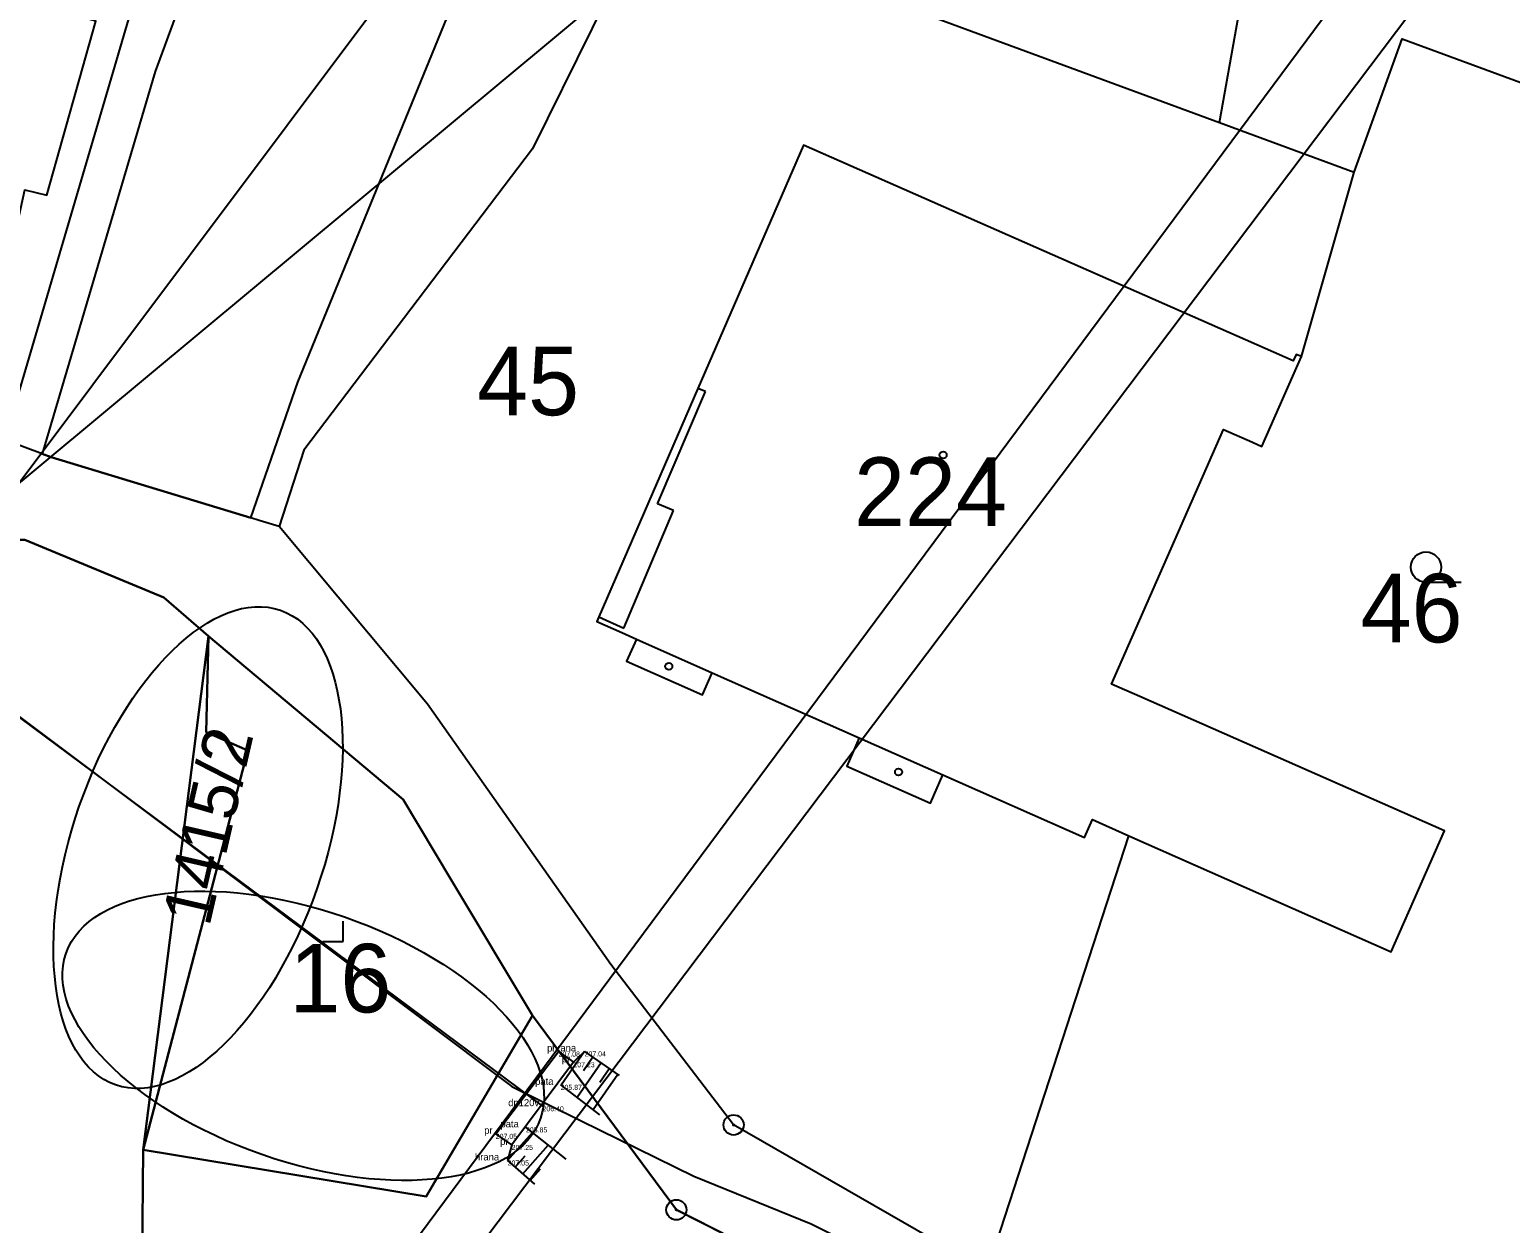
# Model space of a CAD drawing. Extents: x -537341 to -532984, y -1143469 to -1141314.
# Drawn here: x -534057.3 to -533983.8, y -1143098.1 to -1143038.9 of the extents above; entities that cross this region are included whole.
import ezdxf

# ---------------------------------------------------------------- set-up
doc = ezdxf.new("R2010")
doc.units = 0
for name, color, linetype in [('Hranice parcel', 7, 'Continuous'), ('parcelní_č_2000', 7, 'Continuous'), ('u_II_etapa', 7, 'Continuous'), ('u_obec_Horní_Moš', 7, 'Continuous'), ('u_osa_stávající', 7, 'Continuous'), ('u_osa_toku', 7, 'Continuous'), ('u_pricne', 7, 'Continuous'), ('u_ŘSD', 7, 'Continuous'), ('Vnitřní kresba', 7, 'Continuous'), ('Značky bodu BP', 7, 'Continuous'), ('Značky budov', 7, 'Continuous'), ('Značky kultur', 7, 'Continuous'), ('ˇ1', 7, 'Continuous'), ('ˇ12', 7, 'Continuous'), ('ˇ13', 7, 'Continuous'), ('ˇ18', 7, 'Continuous'), ('ˇ3', 7, 'Continuous'), ('ˇ8', 7, 'Continuous'), ('ˇ9', 7, 'Continuous')]:
    doc.layers.add(name, color=color, linetype=linetype)

msp = doc.modelspace()

# ---------------------------------------------------------------- linework, layer by layer
at = {"layer": 'Hranice parcel'}
for p, q in [((-534051.07, -1143040.98), (-534056.69, -1143059.93)), ((-533998.28, -1143043.5), (-533991.6, -1143045.96)), ((-533994.21, -1143055.11), (-533991.6, -1143045.96)), ((-534046.33, -1143063.11), (-534044, -1143056.38)), ((-534056.69, -1143059.93), (-534059.71, -1143058.81)), ((-534051.67, -1143094.44), (-534048.43, -1143068.97)), ((-534009.79, -1143100.45), (-534002.78, -1143078.87)), ((-534051.84, -1143114.55), (-534051.67, -1143094.44))]:
    msp.add_line(p, q, dxfattribs=at)
for points in [[(-534029.93, -1142977.12), (-534030.99, -1142978.87), (-534033.87, -1142990.61), (-534034.9, -1142999.9), (-534043.73, -1143021.03), (-534051.07, -1143040.98)], [(-534044, -1143056.38), (-534033.84, -1143031.57), (-534033.62, -1143024.42), (-534031.82, -1143019.79), (-534025.57, -1143004.98), (-534017.11, -1142985.6), (-534015.33, -1142982.24), (-534014.75, -1142977.48)], [(-534037.83, -1142990.33), (-534051.24, -1143034.42), (-534058.01, -1143057.42), (-534059.71, -1143058.81)], [(-533998.28, -1143043.5), (-533996.76, -1143034.98), (-533991.84, -1143020.44), (-533993.4, -1143019.57)], [(-534023.48, -1143024.37), (-534026.44, -1143032.82), (-534032.36, -1143044.81), (-534043.7, -1143059.75), (-534044.93, -1143063.54)], [(-534023.48, -1143024.37), (-534016.06, -1143027.04), (-534019.25, -1143035.8), (-534011.84, -1143038.52), (-533998.28, -1143043.5)], [(-534061.01, -1143057.76), (-534059.61, -1143051.09), (-534058.54, -1143051.38), (-534057.55, -1143046.84), (-534056.45, -1143047.11), (-534054.02, -1143038.48), (-534068.08, -1143034.65), (-534070.33, -1143043.04), (-534072.14, -1143042.42), (-534074.04, -1143047.26), (-534079.2, -1143053.63)], [(-533991.6, -1143045.96), (-533989.21, -1143039.35), (-533974.11, -1143044.91), (-533978.01, -1143064.66), (-533978.85, -1143064.5), (-533979.24, -1143066.49), (-533976.96, -1143066.84)], [(-533994.21, -1143055.11), (-533994.48, -1143055), (-533994.62, -1143055.32), (-534018.91, -1143044.63), (-534024.15, -1143056.69), (-534029.07, -1143068.02), (-534029.17, -1143068.25), (-534027.93, -1143068.8), (-534027.2, -1143069.12), (-534027.69, -1143070.22), (-534023.93, -1143071.89), (-534023.44, -1143070.79), (-534016.15, -1143074.01), (-534016.77, -1143075.42), (-534012.62, -1143077.25), (-534012, -1143075.85), (-534004.97, -1143078.96), (-534004.57, -1143078.07), (-534002.78, -1143078.87)], [(-534002.78, -1143078.87), (-533989.76, -1143084.63), (-533987.12, -1143078.63), (-534002.23, -1143071.97), (-534003.63, -1143071.35), (-533998.07, -1143058.73), (-533996.64, -1143059.36), (-533996.18, -1143059.57), (-533994.21, -1143055.11)], [(-534056.69, -1143059.93), (-534056.24, -1143060.09), (-534049.16, -1143062.24), (-534046.33, -1143063.11)], [(-534044.93, -1143063.54), (-534045.91, -1143063.24), (-534046.33, -1143063.11)], [(-534009.79, -1143100.45), (-534022.38, -1143093.21), (-534028.47, -1143085.26), (-534037.56, -1143072.35), (-534044.93, -1143063.54)], [(-534048.43, -1143068.97), (-534050.64, -1143067.05), (-534057.55, -1143064.2), (-534057.96, -1143064.19)], [(-534051.67, -1143094.44), (-534046.48, -1143074.64), (-534048.54, -1143073.74), (-534048.43, -1143068.97)], [(-534048.43, -1143068.97), (-534038.78, -1143077.07), (-534036.39, -1143081.05), (-534032.35, -1143087.78)], [(-534032.35, -1143087.78), (-534037.63, -1143096.75), (-534051.67, -1143094.44)], [(-534032.35, -1143087.78), (-534025.22, -1143097.42), (-534003.68, -1143108.33)]]:
    msp.add_lwpolyline(points, dxfattribs=at)
at = {"layer": 'u_II_etapa'}
for centre, major_axis in [((-534048.948, -1143079.456), (-4.091, -11.768)), ((-534048.948, -1143079.456), (-4.091, -11.768)), ((-534043.729, -1143088.789), (-11.768, 4.091)), ((-534043.729, -1143088.789), (-11.768, 4.091))]:
    msp.add_ellipse(centre, major_axis=major_axis, ratio=0.50074, dxfattribs=at)
at = {"layer": 'u_obec_Horní_Moš'}
for p, q in [((-534056.69, -1143059.93), (-534059.71, -1143058.81)), ((-534050.64, -1143067.05), (-534048.43, -1143068.97)), ((-534048.43, -1143068.97), (-534051.67, -1143094.44)), ((-534048.54, -1143073.74), (-534048.43, -1143068.97)), ((-534048.43, -1143068.97), (-534038.78, -1143077.07)), ((-534046.48, -1143074.64), (-534048.54, -1143073.74)), ((-534051.67, -1143094.44), (-534046.48, -1143074.64)), ((-534038.78, -1143077.07), (-534036.39, -1143081.05)), ((-534036.39, -1143081.05), (-534032.35, -1143087.78)), ((-534032.35, -1143087.78), (-534037.63, -1143096.75)), ((-534025.22, -1143097.42), (-534032.35, -1143087.78)), ((-534051.67, -1143094.44), (-534051.84, -1143114.55)), ((-534037.63, -1143096.75), (-534051.67, -1143094.44)), ((-534003.68, -1143108.33), (-534025.22, -1143097.42))]:
    msp.add_line(p, q, dxfattribs=at)
for points in [[(-534046.33, -1143063.11), (-534049.16, -1143062.24), (-534056.24, -1143060.09), (-534056.69, -1143059.93)], [(-534044.93, -1143063.54), (-534045.91, -1143063.24), (-534046.33, -1143063.11)], [(-534009.79, -1143100.45), (-534022.38, -1143093.21), (-534028.47, -1143085.26), (-534037.56, -1143072.35), (-534044.93, -1143063.54)], [(-534057.96, -1143064.19), (-534057.55, -1143064.2), (-534050.64, -1143067.05)], [(-534032.35, -1143087.78), (-534025.22, -1143097.42), (-534003.68, -1143108.33)]]:
    msp.add_lwpolyline(points, dxfattribs=at)
at = {"layer": 'u_osa_stávající'}
msp.add_lwpolyline([(-534029.938, -1143092.998), (-534024.36, -1143095.747), (-534018.539, -1143098.105), (-534002.633, -1143106.063), (-533979.52, -1143113.76), (-533965.652, -1143121.261), (-533942.321, -1143139.25), (-533937.742, -1143147.056), (-533937.262, -1143155.211), (-533938.57, -1143165.939), (-533939.007, -1143180.156), (-533935.954, -1143193.326), (-533920.298, -1143207.368), (-533896.4, -1143226.731), (-533870.016, -1143249.801), (-533856.715, -1143265.326), (-533834.822, -1143282.988), (-533827.265, -1143289.086), (-533803.511, -1143301.304), (-533782.839, -1143320.667), (-533772.417, -1143327.121)], dxfattribs=at)
at = {"layer": 'u_osa_toku'}
msp.add_lwpolyline([(-534255.2, -1143086.242), (-534194.495, -1143118.949), (-534158.208, -1143134.477), (-534141.073, -1143140.275), (-534130.725, -1143142.98), (-534122.661, -1143143.626), (-534114.813, -1143141.462), (-534105.041, -1143135.691), (-534099.556, -1143127.453), (-534095.683, -1143120.128), (-534091.183, -1143106.259), (-534085.121, -1143084.236), (-534081.698, -1143076.975), (-534079.417, -1143074.051), (-534076.981, -1143071.521), (-534075.983, -1143070.507), (-534074.271, -1143069.057), (-534072.483, -1143067.88), (-534069.692, -1143067.171), (-534065.2, -1143067.444), (-534033.387, -1143091.298), (-534029.938, -1143092.998)], dxfattribs=at)
at = {"layer": 'u_pricne'}
for p, q in [((-534094.823, -1143110.698), (-534021.005, -1143012.252)), ((-534008.415, -1143020.259), (-534107.407, -1143102.639)), ((-533988.923, -1143032.655), (-534062.355, -1143131.49)), ((-533986.083, -1143034.462), (-534060.326, -1143132.79))]:
    msp.add_line(p, q, dxfattribs=at)
at = {"layer": 'u_ŘSD'}
for p, q in [((-534051.67, -1143094.44), (-534048.43, -1143068.97)), ((-534032.35, -1143087.78), (-534036.39, -1143081.05)), ((-534051.84, -1143114.55), (-534051.67, -1143094.44))]:
    msp.add_line(p, q, dxfattribs=at)
for points in [[(-534048.43, -1143068.97), (-534050.64, -1143067.05), (-534057.55, -1143064.2), (-534057.96, -1143064.19)], [(-534048.43, -1143068.97), (-534048.54, -1143073.74), (-534046.48, -1143074.64), (-534051.67, -1143094.44)], [(-534036.39, -1143081.05), (-534038.78, -1143077.07), (-534048.43, -1143068.97)], [(-534051.67, -1143094.44), (-534037.63, -1143096.75), (-534032.35, -1143087.78)]]:
    msp.add_lwpolyline(points, dxfattribs=at)
at = {"layer": 'Vnitřní kresba'}
for p, q in [((-534023.78, -1143056.85), (-534024.15, -1143056.69)), ((-534026.15, -1143062.41), (-534023.78, -1143056.85)), ((-534025.36, -1143062.75), (-534026.15, -1143062.41)), ((-534027.83, -1143068.57), (-534025.36, -1143062.75)), ((-534029.07, -1143068.02), (-534027.83, -1143068.57)), ((-534027.2, -1143069.12), (-534023.44, -1143070.79)), ((-534016.15, -1143074.01), (-534012, -1143075.85))]:
    msp.add_line(p, q, dxfattribs=at)
at = {"layer": 'Značky bodu BP'}
for centre, radius in [((-534022.38, -1143093.21), 0.5), ((-534022.38, -1143093.21), 0.0303), ((-534025.22, -1143097.42), 0.5), ((-534025.22, -1143097.42), 0.0303)]:
    msp.add_circle(centre, radius, dxfattribs=at)
at = {"layer": 'Značky budov'}
for centre in [(-534011.987, -1143059.989), (-534025.597, -1143070.469), (-534014.197, -1143075.709)]:
    msp.add_circle(centre, 0.175, dxfattribs=at)
at = {"layer": 'Značky kultur'}
for p, q in [((-533988.033, -1143066.3), (-533986.283, -1143066.3)), ((-534041.75, -1143084.11), (-534041.75, -1143083.11)), ((-534042.751, -1143084.11), (-534041.75, -1143084.11))]:
    msp.add_line(p, q, dxfattribs=at)
msp.add_circle((-533988.033, -1143065.55), 0.75, dxfattribs=at)
at = {"layer": 'ˇ1'}
for p, q in [((-534031.06, -1143089.57), (-534031.06, -1143089.57)), ((-534031.06, -1143089.57), (-534031.06, -1143089.57)), ((-534029.77, -1143089.56), (-534029.77, -1143089.56)), ((-534029.77, -1143089.56), (-534029.77, -1143089.56)), ((-534030.33, -1143090.1), (-534030.33, -1143090.1)), ((-534030.33, -1143090.1), (-534030.33, -1143090.1)), ((-534030.96, -1143091.22), (-534030.96, -1143091.22)), ((-534030.96, -1143091.22), (-534030.96, -1143091.22)), ((-534031.86, -1143092.28), (-534031.86, -1143092.28)), ((-534031.86, -1143092.28), (-534031.86, -1143092.28)), ((-534032.68, -1143093.33), (-534032.68, -1143093.33)), ((-534032.68, -1143093.33), (-534032.68, -1143093.33)), ((-534034.18, -1143093.65), (-534034.18, -1143093.65)), ((-534034.18, -1143093.65), (-534034.18, -1143093.65)), ((-534033.39, -1143094.2), (-534033.39, -1143094.2)), ((-534033.39, -1143094.2), (-534033.39, -1143094.2)), ((-534033.59, -1143094.97), (-534033.59, -1143094.97)), ((-534033.59, -1143094.97), (-534033.59, -1143094.97))]:
    msp.add_line(p, q, dxfattribs=at)
at = {"layer": 'ˇ12'}
for p, q in [((-534029.77, -1143089.56), (-534030.33, -1143090.1)), ((-534029.77, -1143089.56), (-534028.06, -1143090.75)), ((-534030.96, -1143091.22), (-534029.03, -1143092.7)), ((-534032.68, -1143093.33), (-534030.71, -1143094.9)), ((-534033.39, -1143094.2), (-534033.59, -1143094.97)), ((-534033.59, -1143094.97), (-534032.26, -1143096.15))]:
    msp.add_line(p, q, dxfattribs=at)
at = {"layer": 'ˇ13'}
for p, q in [((-534029.77, -1143089.56), (-534030.937, -1143091.237)), ((-534029.36, -1143089.846), (-534029.832, -1143090.524)), ((-534028.949, -1143090.131), (-534030.143, -1143091.847)), ((-534028.539, -1143090.417), (-534029.022, -1143091.11)), ((-534028.128, -1143090.702), (-534029.349, -1143092.456)), ((-534033.59, -1143094.97), (-534032.361, -1143093.584)), ((-534032.842, -1143095.634), (-534031.578, -1143094.208)), ((-534033.216, -1143095.302), (-534032.717, -1143094.74)), ((-534032.468, -1143095.965), (-534031.955, -1143095.388))]:
    msp.add_line(p, q, dxfattribs=at)
at = {"layer": 'ˇ8'}
msp.add_line((-534065.1, -1143067.59), (-534031.86, -1143092.28), dxfattribs=at)
at = {"layer": 'ˇ9'}
for p, q in [((-534034.18, -1143093.65), (-534031.06, -1143089.57)), ((-534031.06, -1143089.57), (-534030.33, -1143090.1)), ((-534030.33, -1143090.1), (-534033.39, -1143094.2)), ((-534033.39, -1143094.2), (-534034.18, -1143093.65))]:
    msp.add_line(p, q, dxfattribs=at)

# ---------------------------------------------------------------- texts
at = {"layer": 'parcelní_č_2000'}
for s, p in [('45', (-534035.104, -1143058.02)), ('224', (-534016.405, -1143063.51)), ('46', (-533991.277, -1143069.28)), ('16', (-534044.419, -1143087.63))]:
    msp.add_text(s, height=3.4, dxfattribs=at).set_placement(p)
msp.add_text('1415/2', height=2.4, rotation=77, dxfattribs=at).set_placement((-534048.393, -1143083.428))
at = {"layer": 'ˇ18'}
for s, p in [('pr', (-534031.633, -1143089.57)), ('hrana', (-534031.39, -1143089.56)), ('pr', (-534030.903, -1143090.1)), ('pata', (-534032.227, -1143091.22)), ('dn120v', (-534033.563, -1143092.28)), ('pr', (-534034.753, -1143093.65)), ('pata', (-534033.947, -1143093.33)), ('pr', (-534033.963, -1143094.2)), ('hrana', (-534035.21, -1143094.97))]:
    msp.add_text(s, height=0.35, dxfattribs=at).set_placement(p)
at = {"layer": 'ˇ3'}
for s, p in [('207.08 ', (-534031.06, -1143089.82)), ('207.04 ', (-534029.77, -1143089.81)), ('207.23 ', (-534030.33, -1143090.35)), ('205.87 ', (-534030.96, -1143091.47)), ('206.40 ', (-534031.86, -1143092.53)), ('205.85 ', (-534032.68, -1143093.58)), ('207.05 ', (-534034.18, -1143093.9)), ('207.25 ', (-534033.39, -1143094.45)), ('207.05 ', (-534033.59, -1143095.22))]:
    msp.add_text(s, height=0.25, dxfattribs=at).set_placement(p)

doc.saveas('drawing.dxf')
